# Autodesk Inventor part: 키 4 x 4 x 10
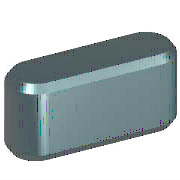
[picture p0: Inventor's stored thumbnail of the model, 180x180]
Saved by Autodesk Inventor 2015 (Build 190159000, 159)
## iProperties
IsCustomPart: 1
Created: 2012-02
Part Number: 키 4 x 4 x 10
Material: 강철, 연강
Description: 키 및 해당 키홈
Document SubType Name: Modeling
Standard: KS B 1311
Designer: mduedu
Standards Organization: KS
Language: ko-KR
Size Designation: 4 x 4 x 10
Categories: <MemberInstance><Categories><Category DisplayName="샤프트 부품" InternalName="7f7aeb1f-a693-4053-b835-cee3144e0d98" Mnemonic="SHFT"><Category DisplayName="키" Interna
Density: 1 g/cm^3
Appearance: 노란색
Author: mduedu
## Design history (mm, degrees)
workplane "Work Plane1"
workplane "Work Plane2"
sketch "스케치1"
  geometry: L1 (2, 2)-(8, 2); L2 (8, -2)-(2, -2); L3 (0, 9.4)-(0, -7.4) reference; L4 (-5, 0)-(30, 0) reference; L5 (10, 0)-(10, 7); A1 r 2 centre (2, 0) between (2, 2) and (2, -2); A2 r 2 centre (8, 0) between (8, -2) and (8, 2)
  constraints: 6 end point, 5 point on circle, 4 tangent, 3 point on line, 2 centre point, 1 horizontal, 1 parallel, 1 perpendicular
  dimensions: "d0" = 2 radius of A1 (= 0.5 x PB); "d13" = 2 radius of A2 (= 0.5 x PB); "d14" = 10 distance between parallel lines of L5 L3 (= NLG)
extrude "본체1" new body sketch "스케치1" taper "d3" = 0 deg; stored distance "d4" = 10
workplane "Work Plane3"
body "Solid1"
chamfer "모따기1" distance "d8" = 0.25 (= PHH); stored, may be unused: second distance "d9" = 0.25 (= PHH), angle "d15" = 45 deg
other parameters: "d1" = -2.5 (= -PNT), "d2" = 1.5 (= PH - PNT), "NLG" = 10 [user parameter; used in 3 equation terms], "PB" = 4 [user parameter; used in 2 equation terms], "PNT" = 2.5 [user parameter; used in 2 equation terms], "PH" = 4 [user parameter; used in 1 equation term], "PHH" = 0.25 [user parameter; used in 2 equation terms], "d10" = 0, "d16" = 0, "d17" = 0, "d18" = 0, "WDMAX" = 12 [user parameter], "RR" = 0.08 [user parameter], "PUEB" = 1.8 [user parameter]
